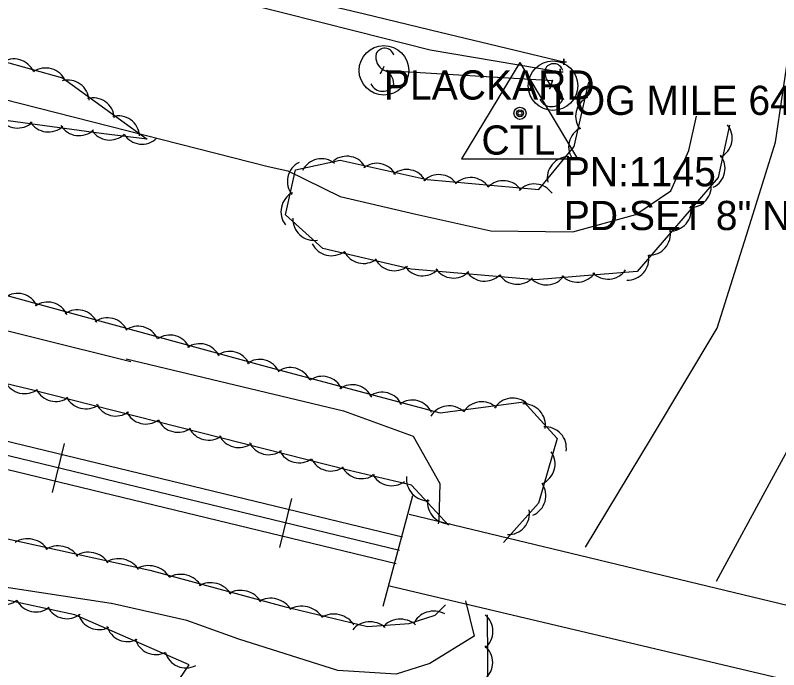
# Model space of a CAD drawing. Extents: x 1441650 to 1491889, y 345904 to 358319.
# Drawn here: x 1452325 to 1452455.6, y 352835.5 to 352947.5 of the extents above; entities that cross this region are included whole.
import ezdxf

# ---------------------------------------------------------------- set-up
doc = ezdxf.new("R2010")
doc.units = 0
for name, color, linetype in [('S_BRIDGE', 7, 'Continuous'), ('S_DITCHLINE', 7, 'Continuous'), ('S_EDGE_PAVEMENT', 7, 'Continuous'), ('S_GUARDRAIL', 7, 'Continuous'), ('S_MSC_PT_SYM', 7, 'Continuous'), ('S_PRIMARY_CTL', 7, 'Continuous'), ('S_PRIMARY_CTL_ANNOT', 7, 'Continuous'), ('S_RAILROAD', 7, 'Continuous'), ('S_RDW_PT_SYM', 7, 'Continuous'), ('S_SHOULDER', 7, 'Continuous'), ('S_SIGN', 7, 'Continuous'), ('S_SIGN_ANNOT', 7, 'Continuous'), ('S_STR_PT_SYM', 7, 'Continuous'), ('S_STREAM', 7, 'Continuous'), ('S_TREE', 7, 'Continuous')]:
    doc.layers.add(name, color=color, linetype=linetype)

msp = doc.modelspace()

# ---------------------------------------------------------------- linework, layer by layer
at = {"layer": 'S_BRIDGE'}
for p, q in [((1452387.93, 352846.33), (1452393, 352865.26)), ((1452392.39, 352862.07), (1452498.21, 352836.64)), ((1452495.28, 352824.58), (1452389.01, 352849.78))]:
    msp.add_line(p, q, dxfattribs=at)
at = {"layer": 'S_DITCHLINE'}
for points in [[(1452422.55, 352856.44), (1452433.83, 352875.18), (1452445.12, 352893.93), (1452450.09, 352909.84), (1452455.06, 352925.76), (1452457.49, 352941.97), (1452459.92, 352958.19), (1452462.78, 352972.95), (1452465.63, 352987.72), (1452468.49, 353002.49), (1452471.34, 353017.26)], [(1452445, 352850.6), (1452454.41, 352867.95), (1452463.83, 352885.3), (1452465.62, 352904.42), (1452467.41, 352923.54), (1452470.87, 352941.54), (1452474.32, 352959.53), (1452477.21, 352972.3), (1452480.11, 352985.06), (1452477.57, 353006.59)]]:
    msp.add_lwpolyline(points, dxfattribs=at)
at = {"layer": 'S_EDGE_PAVEMENT'}
msp.add_lwpolyline([(1452079.1, 353021.43), (1452091.95, 353018.36), (1452104.81, 353015.29), (1452128.21, 353009.6), (1452151.61, 353003.91), (1452174.5, 352998.45), (1452197.38, 352992.99), (1452210.68, 352989.79), (1452223.99, 352986.59), (1452237.29, 352983.39), (1452250.59, 352980.19), (1452272.6, 352974.85), (1452294.6, 352969.52), (1452307.4, 352966.43), (1452320.2, 352963.35), (1452333, 352960.26), (1452345.8, 352957.17), (1452358.78, 352954.03), (1452371.76, 352950.88), (1452384.73, 352947.74), (1452397.71, 352944.6), (1452418.84, 352939.54)], dxfattribs=at)
at = {"layer": 'S_GUARDRAIL'}
msp.add_line((1452388.62, 352938.07), (1452416.92, 352936.32), dxfattribs=at)
at = {"layer": 'S_MSC_PT_SYM'}
for points in [[(1452388.08, 352938.71), (1452388.08, 352938.76), (1452388.08, 352938.71), (1452388.03, 352938.71), (1452388.08, 352938.71), (1452388.08, 352938.66), (1452388.08, 352938.71), (1452388.13, 352938.71)], [(1452387.5, 352937.6), (1452387.5, 352937.65), (1452387.5, 352937.6), (1452387.45, 352937.6), (1452387.5, 352937.6), (1452387.5, 352937.55), (1452387.5, 352937.6), (1452387.55, 352937.6)], [(1452416.85, 352936.15), (1452416.85, 352936.2), (1452416.85, 352936.15), (1452416.8, 352936.15), (1452416.85, 352936.15), (1452416.85, 352936.1), (1452416.85, 352936.15), (1452416.9, 352936.15)], [(1452416.45, 352934.99), (1452416.45, 352935.04), (1452416.45, 352934.99), (1452416.4, 352934.99), (1452416.45, 352934.99), (1452416.45, 352934.94), (1452416.45, 352934.99), (1452416.5, 352934.99)]]:
    msp.add_lwpolyline(points, dxfattribs=at)
at = {"layer": 'S_PRIMARY_CTL'}
for p, q in [((1452411.35, 352939.43), (1452401.32, 352922.92)), ((1452411.35, 352939.43), (1452421.17, 352922.92)), ((1452401.32, 352922.92), (1452421.17, 352922.92))]:
    msp.add_line(p, q, dxfattribs=at)
for radius in [1.04, 0.609, 0.344]:
    msp.add_circle((1452411.35, 352930.73), radius, dxfattribs=at)
at = {"layer": 'S_RAILROAD'}
for p, q in [((1452331.38, 352865.78), (1452333.43, 352874.21)), ((1452332.96, 352872.26), (1452332.93, 352872.16)), ((1452331.85, 352867.69), (1452331.86, 352867.72)), ((1452370.26, 352856.36), (1452372.3, 352864.79)), ((1452371.83, 352862.84), (1452371.81, 352862.74)), ((1452370.72, 352858.27), (1452370.73, 352858.3))]:
    msp.add_line(p, q, dxfattribs=at)
for points in [[(1452391.27, 352858.13), (1451315.37, 353118.79)], [(1452390.72, 352855.86), (1451314.82, 353116.52)], [(1452390.16, 352853.56), (1451314.26, 353114.21)], [(1452332.43, 352869.98), (1452332.41, 352869.99)], [(1452371.31, 352860.57), (1452371.28, 352860.57)]]:
    msp.add_lwpolyline(points, dxfattribs=at)
at = {"layer": 'S_RDW_PT_SYM'}
for points in [[(1452388.62, 352938.07), (1452388.62, 352938.12), (1452388.62, 352938.07), (1452388.57, 352938.07), (1452388.62, 352938.07), (1452388.62, 352938.02), (1452388.62, 352938.07), (1452388.67, 352938.07)], [(1452416.92, 352936.32), (1452416.92, 352936.37), (1452416.92, 352936.32), (1452416.87, 352936.32), (1452416.92, 352936.32), (1452416.92, 352936.27), (1452416.92, 352936.32), (1452416.97, 352936.32)]]:
    msp.add_lwpolyline(points, dxfattribs=at)
at = {"layer": 'S_SHOULDER'}
msp.add_lwpolyline([(1452078.65, 353018.96), (1452091.46, 353015.87), (1452104.26, 353012.78), (1452127.72, 353007.08), (1452151.18, 353001.39), (1452174, 352996), (1452196.82, 352990.6), (1452210.08, 352987.39), (1452223.35, 352984.18), (1452236.61, 352980.97), (1452249.87, 352977.75), (1452271.98, 352972.31), (1452294.08, 352966.87), (1452306.93, 352963.75), (1452319.78, 352960.63), (1452332.63, 352957.51), (1452345.47, 352954.39), (1452358.1, 352951.2), (1452370.72, 352948.01), (1452383.35, 352944.81), (1452395.98, 352941.62), (1452418.24, 352937.85)], dxfattribs=at)
at = {"layer": 'S_SIGN'}
for p, q in [((1452388.08, 352938.71), (1452387.5, 352937.6)), ((1452416.85, 352936.15), (1452416.45, 352934.99))]:
    msp.add_line(p, q, dxfattribs=at)
for centre in [(1452388.07, 352938.08), (1452417, 352935.45)]:
    msp.add_circle(centre, 4.24, dxfattribs=at)
for centre, radius, start, end in [((1452388.2, 352940.24), 1.62, 16.5258, 156.8957), ((1452389.24, 352940.34), 2.55, 167.1196, 241.9813), ((1452417.13, 352937.6), 1.62, 16.5258, 156.8957), ((1452387.37, 352935.8), 2.38, 358.6529, 73.7063), ((1452418.17, 352937.7), 2.55, 167.1196, 241.9813), ((1452387.81, 352936.68), 2.17, 204.641, 335.359), ((1452416.3, 352933.16), 2.38, 358.6529, 73.7063), ((1452416.74, 352934.05), 2.17, 204.641, 335.359)]:
    msp.add_arc(centre, radius, start, end, dxfattribs=at)
at = {"layer": 'S_STR_PT_SYM'}
for points in [[(1452418.83, 352939.55), (1452418.83, 352940.05), (1452418.83, 352939.55), (1452418.33, 352939.55), (1452418.83, 352939.55), (1452418.83, 352939.05), (1452418.83, 352939.55), (1452419.33, 352939.55)], [(1452418.23, 352937.85), (1452418.23, 352938.35), (1452418.23, 352937.85), (1452417.73, 352937.85), (1452418.23, 352937.85), (1452418.23, 352937.35), (1452418.23, 352937.85), (1452418.73, 352937.85)]]:
    msp.add_lwpolyline(points, dxfattribs=at)
at = {"layer": 'S_STREAM'}
for points in [[(1451761.2, 352984.03), (1451829.92, 352966.49), (1451908.23, 352948.92), (1451988.74, 352929.34), (1452105.17, 352903.77), (1452208.98, 352879), (1452288.64, 352859.53), (1452296.9, 352854.48), (1452309.22, 352851.75), (1452341.4, 352846.85)], [(1452121.42, 352976.42), (1452153.5, 352970.17), (1452189.76, 352962.15), (1452208.49, 352958.82), (1452280.02, 352942.92), (1452319.86, 352933.96), (1452368.25, 352921.63), (1452371.63, 352920.88), (1452380.59, 352916.48), (1452393.52, 352913.47), (1452406.38, 352910.63), (1452420.38, 352910.43), (1452431.16, 352913.41), (1452437.17, 352917.47), (1452440.23, 352924.37), (1452441.53, 352930.26)], [(1452344.74, 352888.17), (1452167.71, 352932.3), (1452112.86, 352945.49)], [(1452343.95, 352888.67), (1452381.14, 352879.78), (1452393.05, 352875.46), (1452397.61, 352867.35), (1452397.48, 352861.01), (1452397.34, 352860.43)], [(1452402.02, 352847.25), (1452403.53, 352841.21), (1452395.93, 352836.54), (1452390.17, 352834.72), (1452380.21, 352835.3), (1452363.27, 352840.71), (1452354.34, 352843.9), (1452341.43, 352846.79)]]:
    msp.add_lwpolyline(points, dxfattribs=at)
at = {"layer": 'S_TREE'}
for points in [[(1452399.14, 352860.23), (1452392.79, 352867.03), (1452382.12, 352869.59), (1452327.3, 352883.47), (1452173.6, 352920.35), (1452113.09, 352935.02), (1451909.03, 352985.34), (1451768.73, 353018.48), (1451597.59, 353062.21), (1451520.63, 353079.57), (1451497.6, 353087.01), (1451451.58, 353107.05), (1451431.16, 353111.57), (1451407.97, 353109.12), (1451350.29, 353121.94)], [(1451327.8, 353097.43), (1451402.02, 353075.91), (1451483.15, 353063.22), (1451576.93, 353036.02), (1451646.54, 353020.05), (1451689.99, 353010.43), (1451796.02, 352984.25), (1451899.97, 352960.18), (1451949.9, 352948.34), (1452006.53, 352935.3), (1452073.14, 352918.73), (1452124.03, 352905.6), (1452167.72, 352893.63), (1452197.97, 352887.99), (1452238.01, 352878.56), (1452281.14, 352868.99), (1452322.62, 352858.1), (1452348, 352852.48), (1452371.02, 352846.3), (1452385.26, 352842.85), (1452392.41, 352843.39), (1452396.82, 352844.8), (1452398.6, 352846.57)], [(1452054.5, 353001.3), (1452108.24, 352989.27), (1452162.46, 352975.14), (1452222.9, 352961.76), (1452263.51, 352952.77), (1452297.36, 352945.96), (1452311.79, 352942.74), (1452333.07, 352936.81), (1452347.56, 352926.32), (1452339.67, 352927.26), (1452310.29, 352931.24), (1452287.14, 352936.31), (1452264.66, 352941.06), (1452249.93, 352939.61), (1452228.27, 352944.27), (1452205.3, 352954.48), (1452184.36, 352963.54), (1452158.31, 352969.3), (1452126.27, 352975.85), (1452103.73, 352977.64), (1452080.41, 352979.97)], [(1452071.11, 352968.43), (1452109.87, 352950.96), (1452139.85, 352950.84), (1452164.78, 352936.08), (1452199.57, 352927.55), (1452228.61, 352921.09), (1452282.18, 352909.23), (1452313.52, 352902.26), (1452368.38, 352887.25), (1452397.7, 352879.43), (1452412.01, 352881.33), (1452417.7, 352875.05), (1452414.53, 352863.96), (1452408.56, 352857.22)], [(1452447.23, 352928.68), (1452445.25, 352919.72), (1452431.4, 352903.65), (1452413.98, 352902.19), (1452392.71, 352904.05), (1452377.64, 352907.58), (1452371.23, 352913.33), (1452372.94, 352921.03), (1452380.6, 352922.7), (1452395.47, 352919.41), (1452414.6, 352917.66), (1452420.65, 352925.05), (1452423.13, 352936.03)], [(1452344.18, 352820.84), (1452354.74, 352836.3), (1452335.19, 352844.87), (1452296.34, 352853.22), (1452279.04, 352855.15), (1452267.66, 352838.48), (1452253.31, 352851.41), (1452235.36, 352859.93), (1452217.41, 352857.17), (1452208.81, 352867.89), (1452192.63, 352857.96), (1452172.54, 352875.39), (1452153.1, 352874.94), (1452127.6, 352877.87), (1452109.81, 352875.6), (1452091.94, 352900.54), (1452069.93, 352896.14)], [(1452405.72, 352844.84), (1452405.95, 352813.94), (1452401.24, 352796.48), (1452389.48, 352776.78), (1452372.29, 352760.34), (1452368.77, 352736.72), (1452376.62, 352716.4), (1452375.04, 352708.04)]]:
    msp.add_lwpolyline(points, dxfattribs=at)
for centre, start, end in [((1452444.02, 352926.5), 296.7186, 38.3155), ((1452442.8, 352921.31), 296.7186, 38.3155), ((1452375.19, 352919.07), 116.7186, 218.3155), ((1452374.08, 352913.88), 116.7186, 218.3155)]:
    msp.add_arc(centre, 3.64, start, end, dxfattribs=at)
for centre, major_axis, ratio, start_param, end_param in [((1452324.78, 352936.4), (-3.52, 0.94), 0.997457, 3.815788, 5.588989), ((1452330.21, 352934.85), (-3.52, 0.94), 0.997457, 3.815788, 5.588989), ((1452333.98, 352932.79), (-3.64, 0.16), 0.996861, 3.243263, 5.016463), ((1452338.29, 352929.75), (-3.64, 0.16), 0.996861, 3.243263, 5.016463), ((1452424.51, 352930.2), (3.55, -0.83), 0.988578, 2.261348, 4.034549), ((1452325.4, 352931.84), (3.44, -1.19), 0.997384, 4.025498, 5.798699), ((1452342.61, 352926.67), (-3.64, 0.16), 0.996861, 3.243263, 5.016463), ((1452330.66, 352931.16), (3.44, -1.19), 0.997384, 4.025498, 5.798699), ((1452335.9, 352930.53), (3.44, -1.19), 0.997384, 4.025498, 5.798699), ((1452341.1, 352929.77), (1.16, -3.45), 0.986025, 4.958798, 6.731998), ((1452346.64, 352929.07), (1.16, -3.45), 0.986025, 4.958798, 6.731998), ((1452423.32, 352924.96), (3.55, -0.83), 0.988578, 2.261348, 4.034549), ((1452377.38, 352919.31), (0.71, -3.57), 0.988549, 2.274976, 4.048176), ((1452381.7, 352919.74), (-0.86, -3.54), 0.990321, 2.275775, 4.048975), ((1452419.67, 352919.65), (2.14, -2.95), 0.999964, 2.509723, 4.282923), ((1452386.84, 352918.52), (-0.86, -3.54), 0.990321, 2.275775, 4.048975), ((1452391.96, 352917.46), (-0.86, -3.54), 0.990321, 2.275775, 4.048975), ((1452397.49, 352916.59), (-0.06, -3.64), 0.99919, 2.18086, 3.954061), ((1452402.9, 352916.09), (-0.06, -3.64), 0.99919, 2.18086, 3.954061), ((1452408.52, 352915.55), (-0.06, -3.64), 0.99919, 2.18086, 3.954061), ((1452413.82, 352914.99), (-0.06, -3.64), 0.99919, 2.18086, 3.954061), ((1452440.45, 352918.23), (3.61, -0.47), 0.999992, 4.814502, 6.587703), ((1452437.01, 352914.19), (3.61, -0.47), 0.999992, 4.814502, 6.587703), ((1452376.13, 352912.61), (2.71, -2.43), 0.999998, 3.825788, 5.598988), ((1452433.46, 352910.07), (3.61, -0.47), 0.999992, 4.814502, 6.587703), ((1452379.08, 352909.98), (3.55, -0.83), 0.999996, 3.825788, 5.598989), ((1452384.57, 352908.66), (3.55, -0.83), 0.999996, 3.825789, 5.598989), ((1452429.75, 352905.81), (3.61, -0.47), 0.999992, 4.814502, 6.587703), ((1452389.86, 352907.42), (3.55, -0.83), 0.999996, 3.825789, 5.598989), ((1452394.7, 352906.55), (3.51, 0.96), 0.999995, 3.470558, 5.243759), ((1452399.97, 352906.16), (3.51, 0.96), 0.999995, 3.470558, 5.243759), ((1452405.28, 352905.62), (3.51, 0.96), 0.999995, 3.470558, 5.243759), ((1452426.41, 352905.97), (3.19, 1.76), 0.999994, 3.406992, 5.180193), ((1452410.9, 352905.09), (3.51, 0.96), 0.999995, 3.470559, 5.243759), ((1452415.87, 352904.98), (3.19, 1.76), 0.999994, 3.406993, 5.180193), ((1452421.15, 352905.46), (3.19, 1.76), 0.999994, 3.406992, 5.180193), ((1452325.38, 352896.26), (-3.51, 0.96), 0.997457, 3.825789, 5.598989), ((1452330.51, 352894.78), (-3.51, 0.96), 0.997457, 3.825789, 5.598989), ((1452335.62, 352893.46), (-3.51, 0.96), 0.997457, 3.825789, 5.598989), ((1452340.75, 352892.09), (-3.51, 0.96), 0.997457, 3.825789, 5.598989), ((1452346, 352890.65), (-3.51, 0.96), 0.997457, 3.825789, 5.598989), ((1452351.44, 352889.13), (-3.51, 0.96), 0.997457, 3.825789, 5.598989), ((1452356.56, 352887.65), (-3.51, 0.96), 0.997457, 3.825789, 5.598989), ((1452361.68, 352886.33), (-3.51, 0.96), 0.997457, 3.825789, 5.598989), ((1452366.8, 352884.96), (-3.51, 0.96), 0.997457, 3.825789, 5.598989), ((1452372.07, 352883.55), (-3.52, 0.94), 0.997456, 3.825789, 5.598989), ((1452377.52, 352882.06), (-3.52, 0.94), 0.997456, 3.825789, 5.598989), ((1452326.57, 352886.28), (3.54, -0.87), 0.973762, 3.830824, 5.604024), ((1452382.66, 352880.62), (-3.52, 0.94), 0.997456, 3.825789, 5.598989), ((1452331.87, 352884.95), (3.48, -1.07), 0.973685, 3.878357, 5.651558), ((1452387.78, 352879.33), (-3.52, 0.94), 0.997456, 3.825789, 5.598989), ((1452337.02, 352883.68), (3.48, -1.07), 0.973685, 3.878357, 5.651558), ((1452392.91, 352878), (-3.52, 0.94), 0.997456, 3.825789, 5.598989), ((1452404.81, 352877.7), (-2.72, -2.43), 0.996768, 3.227697, 5.000898), ((1452410.1, 352878.33), (-2.72, -2.43), 0.996768, 3.227697, 5.000898), ((1452342.16, 352882.45), (3.48, -1.07), 0.973685, 3.878357, 5.651558), ((1452399.21, 352876.99), (-2.72, -2.43), 0.996768, 3.227697, 5.000898), ((1452412.06, 352877.32), (-2.45, 2.7), 0.998239, 3.825789, 5.598989), ((1452347.31, 352881.08), (3.48, -1.07), 0.973685, 3.878357, 5.651558), ((1452352.78, 352879.66), (3.48, -1.07), 0.973685, 3.878357, 5.651558), ((1452358.05, 352878.32), (3.48, -1.07), 0.973685, 3.878357, 5.651558), ((1452415.65, 352873.42), (-2.45, 2.7), 0.998239, 3.825789, 5.598989), ((1452363.2, 352877.05), (3.48, -1.07), 0.973685, 3.878357, 5.651558), ((1452368.34, 352875.83), (3.48, -1.07), 0.973685, 3.878357, 5.651558), ((1452373.49, 352874.45), (3.48, -1.07), 0.973685, 3.878357, 5.651558), ((1452413.72, 352870.7), (1, 3.5), 0.999997, 3.825789, 5.598989), ((1452378.96, 352873.03), (3.48, -1.07), 0.973685, 3.878357, 5.651558), ((1452384.21, 352871.72), (3.54, -0.85), 0.973763, 3.825789, 5.598989), ((1452389.38, 352870.52), (3.54, -0.85), 0.973763, 3.825789, 5.598989), ((1452395.54, 352868.02), (2.5, -2.65), 0.981211, 3.821404, 5.594605), ((1452412.14, 352865.28), (1, 3.5), 0.999997, 3.825788, 5.598989), ((1452399.13, 352864.07), (2.5, -2.65), 0.981211, 3.821404, 5.594605), ((1452409.35, 352862.24), (1.8, 3.17), 0.99943, 3.617171, 5.390372), ((1452327.33, 352854.73), (-3.56, 0.79), 0.854394, 3.825789, 5.598989), ((1452332.53, 352853.51), (-3.56, 0.79), 0.854394, 3.825789, 5.598989), ((1452337.7, 352852.43), (-3.56, 0.79), 0.854394, 3.825789, 5.598989), ((1452342.89, 352851.32), (-3.56, 0.79), 0.854394, 3.825789, 5.598989), ((1452348.09, 352850.13), (-3.52, 0.94), 0.854432, 3.825789, 5.598989), ((1452353.54, 352848.64), (-3.52, 0.94), 0.854432, 3.825789, 5.598989), ((1452358.68, 352847.2), (-3.52, 0.94), 0.854432, 3.825789, 5.598989), ((1452363.79, 352845.89), (-3.52, 0.94), 0.854432, 3.825789, 5.598989), ((1452323, 352850.21), (0.86, -3.54), 0.999356, 4.945419, 6.71862), ((1452328.51, 352848.99), (0.86, -3.54), 0.999356, 4.945419, 6.71862), ((1452368.92, 352844.55), (-3.52, 0.94), 0.854432, 3.825789, 5.598989), ((1452333.82, 352847.84), (0.86, -3.54), 0.999356, 4.945419, 6.71862), ((1452374.25, 352843.21), (-3.54, 0.85), 0.854355, 3.82372, 5.596921), ((1452339.32, 352845.96), (3.34, -1.46), 0.999887, 3.825789, 5.598989), ((1452379.73, 352841.85), (-3.54, 0.85), 0.854355, 3.82372, 5.596921), ((1452396.64, 352842.28), (-3.64, 0.18), 0.878929, 4.228966, 6.002166), ((1452403.09, 352842.02), (-2.64, 2.51), 0.995729, 3.019771, 4.792971), ((1452385.85, 352840.51), (-3.58, 0.69), 0.858421, 4.135044, 5.908245), ((1452391.04, 352840.97), (-3.58, 0.69), 0.858421, 4.135044, 5.908245), ((1452344.19, 352843.91), (3.34, -1.46), 0.999887, 3.825789, 5.598989), ((1452349.04, 352841.7), (3.34, -1.46), 0.999887, 3.825789, 5.598989), ((1452403.05, 352836.7), (-2.64, 2.51), 0.995729, 3.019771, 4.792971), ((1452354.2, 352839.4), (3.34, -1.46), 0.999887, 3.825789, 5.598989)]:
    msp.add_ellipse(centre, major_axis=major_axis, ratio=ratio, start_param=start_param, end_param=end_param, dxfattribs=at)

# ---------------------------------------------------------------- texts
at = {"layer": 'S_PRIMARY_CTL'}
msp.add_text('CTL', height=5, rotation=360, dxfattribs=at).set_placement((1452404.76, 352923.65))
at = {"layer": 'S_PRIMARY_CTL_ANNOT'}
for s, p in [('PN:1145', (1452418.85, 352918.23)), ('PD:SET 8" NAIL TRIG ELEV', (1452418.85, 352910.73))]:
    msp.add_text(s, height=5, dxfattribs=at).set_placement(p)
at = {"layer": 'S_SIGN_ANNOT'}
for s, p in [('PLACKARD', (1452388.07, 352933.08)), ('LOG MILE 64.11 2.43', (1452417, 352930.45))]:
    msp.add_text(s, height=5, dxfattribs=at).set_placement(p)

doc.saveas('drawing.dxf')
